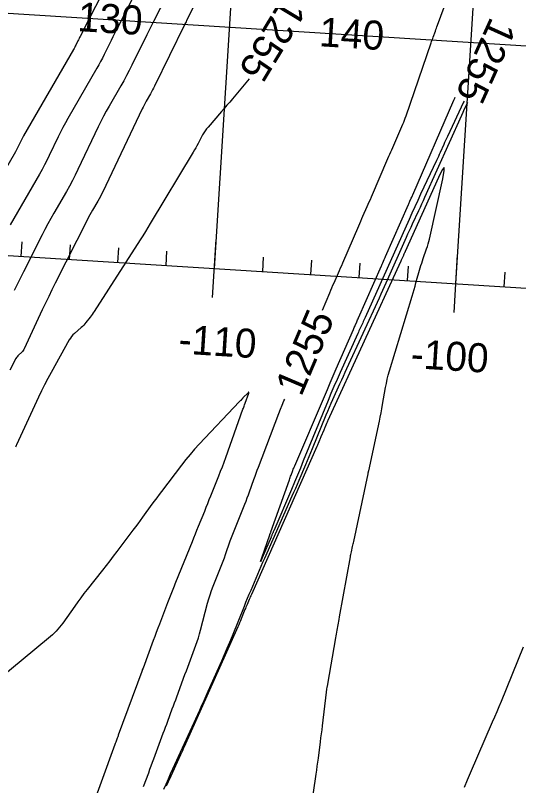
# Model space of a CAD drawing. Extents: x 658976 to 668721, y 639543 to 647196.
# Drawn here: x 661779.9 to 661883.9, y 641733.2 to 641892.5 of the extents above; entities that cross this region are included whole.
import ezdxf

# ---------------------------------------------------------------- set-up
doc = ezdxf.new("R2010")
doc.units = 0
for name, color, linetype in [('Ex_Contour Labels', 7, 'Continuous'), ('Ex_Major Contours', 7, 'Continuous'), ('Ex_Minor Contours', 7, 'Continuous'), ('R_Axis', 7, 'Continuous'), ('R_Axis Annot', 7, 'Continuous'), ('R_Grid', 7, 'Continuous')]:
    doc.layers.add(name, color=color, linetype=linetype)

msp = doc.modelspace()

# ---------------------------------------------------------------- linework, layer by layer
at = {"layer": 'Ex_Major Contours'}
for points in [[(661843.38, 641831.54), (661844.88, 641835.13), (661845.09, 641835.65), (661845.31, 641836.17), (661845.54, 641836.68), (661845.76, 641837.2), (661846.67, 641839.25), (661846.9, 641839.77), (661847.12, 641840.28), (661847.35, 641840.8), (661847.57, 641841.31), (661850.87, 641848.97), (661851.08, 641849.47), (661851.3, 641849.97), (661851.52, 641850.47), (661851.74, 641850.96), (661852.62, 641852.96), (661852.84, 641853.45), (661853.06, 641853.95), (661853.27, 641854.45), (661853.49, 641854.95), (661856.91, 641862.9), (661857.1, 641863.35), (661857.3, 641863.8), (661857.49, 641864.25), (661857.69, 641864.7), (661859.98, 641869.97), (661860.16, 641870.4), (661860.33, 641870.84), (661860.5, 641871.27), (661860.65, 641871.71), (661865.84, 641886.8), (661865.94, 641887.1), (661866.05, 641887.41), (661866.16, 641887.72), (661866.27, 641888.02), (661866.71, 641889.25), (661866.82, 641889.55), (661866.93, 641889.86), (661867.04, 641890.16), (661867.15, 641890.47), (661870.82, 641900.42)], [(661828.23, 641879.36), (661824.76, 641875.24), (661824.2, 641874.57), (661823.64, 641873.91), (661823.07, 641873.25), (661822.51, 641872.59), (661819.75, 641869.4), (661819.43, 641869.01), (661819.14, 641868.61), (661818.86, 641868.19), (661818.61, 641867.76), (661817.66, 641865.98), (661817.41, 641865.54), (661817.17, 641865.1), (661816.92, 641864.67), (661816.66, 641864.23), (661807.79, 641849.43), (661807.28, 641848.6), (661806.77, 641847.77), (661806.25, 641846.94), (661805.73, 641846.11), (661796.19, 641831.26), (661796, 641830.96), (661795.8, 641830.67), (661795.59, 641830.38), (661795.37, 641830.1), (661794.49, 641828.97), (661794.27, 641828.7), (661794.03, 641828.43), (661793.78, 641828.18), (661793.52, 641827.94), (661792.12, 641826.7), (661791.81, 641826.41), (661791.53, 641826.09), (661791.27, 641825.75), (661791.05, 641825.38), (661787.28, 641818.64), (661786.59, 641817.38), (661785.93, 641816.12), (661785.29, 641814.83), (661784.68, 641813.54), (661780.14, 641803.72), (661780.06, 641803.54), (661779.98, 641803.37), (661779.9, 641803.2)], [(661873.33, 641874.45), (661873.28, 641874.33), (661872.99, 641873.7), (661872.69, 641873.07), (661872.4, 641872.43), (661872.12, 641871.8), (661864.49, 641854.81), (661864.18, 641854.12), (661863.87, 641853.43), (661863.55, 641852.74), (661863.23, 641852.05), (661861.94, 641849.3), (661861.62, 641848.61), (661861.3, 641847.92), (661860.98, 641847.23), (661860.67, 641846.54), (661856.46, 641837.14), (661856.11, 641836.37), (661855.76, 641835.59), (661855.41, 641834.82), (661855.06, 641834.05), (661848.37, 641819.43), (661848.01, 641818.63), (661847.64, 641817.83), (661847.28, 641817.03), (661846.92, 641816.22), (661845.47, 641813.02), (661845.11, 641812.22), (661844.76, 641811.41), (661844.41, 641810.6), (661844.08, 641809.79), (661841.22, 641802.84), (661840.89, 641802.02), (661840.55, 641801.2), (661840.2, 641800.38), (661839.86, 641799.56), (661838.47, 641796.3), (661838.12, 641795.48), (661837.77, 641794.67), (661837.41, 641793.86), (661837.06, 641793.05), (661831.37, 641780.17), (661831.01, 641779.35), (661830.65, 641778.52), (661830.29, 641777.7), (661829.94, 641776.87), (661828.54, 641773.55), (661828.19, 641772.72), (661827.84, 641771.89), (661827.5, 641771.06), (661827.16, 641770.22), (661824.7, 641764.12), (661824.17, 641762.82), (661823.63, 641761.54), (661823.08, 641760.25), (661822.52, 641758.98), (661819.7, 641752.66), (661819.26, 641751.69), (661818.83, 641750.72), (661818.39, 641749.75), (661817.95, 641748.78), (661812.41, 641736.64), (661811.93, 641735.58), (661811.45, 641734.52), (661810.98, 641733.47), (661810.5, 641732.41)], [(661806.42, 641733.02), (661807.46, 641735.89), (661807.72, 641736.61), (661807.99, 641737.32), (661808.25, 641738.04), (661808.52, 641738.76), (661810.48, 641744.04), (661810.71, 641744.67), (661810.94, 641745.3), (661811.18, 641745.93), (661811.41, 641746.56), (661812.34, 641749.08), (661812.57, 641749.71), (661812.8, 641750.34), (661813.04, 641750.97), (661813.27, 641751.6), (661814.96, 641756.17), (661815.24, 641756.93), (661815.53, 641757.69), (661815.81, 641758.45), (661816.09, 641759.21), (661817.21, 641762.26), (661817.48, 641763.02), (661817.74, 641763.79), (661817.97, 641764.57), (661818.18, 641765.35), (661819.62, 641770.92), (661819.86, 641771.82), (661820.14, 641772.7), (661820.44, 641773.58), (661820.78, 641774.45), (661822.31, 641778.25), (661822.58, 641778.94), (661822.84, 641779.63), (661823.1, 641780.32), (661823.35, 641781.02), (661824.33, 641783.81), (661824.58, 641784.5), (661824.84, 641785.2), (661825.1, 641785.89), (661825.37, 641786.57), (661827.34, 641791.43), (661827.59, 641792.06), (661827.83, 641792.7), (661828.07, 641793.34), (661828.3, 641793.97), (661829.21, 641796.54), (661829.44, 641797.18), (661829.67, 641797.81), (661829.91, 641798.45), (661830.15, 641799.09), (661834.38, 641810.16), (661834.72, 641811.04), (661835.07, 641811.91), (661835.42, 641812.77), (661835.57, 641813.12)], [(661872.75, 641732.88), (661873.35, 641734.39), (661873.98, 641735.87), (661878.54, 641746.4), (661879, 641747.46), (661879.46, 641748.53), (661879.9, 641749.6), (661880.35, 641750.68), (661884.95, 641761.94)]]:
    msp.add_lwpolyline(points, dxfattribs=at)
at = {"layer": 'Ex_Minor Contours'}
for points in [[(661806.03, 641913.15), (661793.29, 641888.14), (661793.17, 641887.92), (661793.06, 641887.7), (661792.95, 641887.47), (661792.84, 641887.25), (661792.4, 641886.35), (661792.29, 641886.12), (661792.17, 641885.9), (661792.05, 641885.68), (661791.93, 641885.46), (661781.59, 641867.56), (661781.44, 641867.29), (661781.29, 641867.02), (661781.15, 641866.75), (661781.02, 641866.47), (661780.49, 641865.36), (661780.35, 641865.08), (661780.21, 641864.8), (661780.07, 641864.53), (661779.91, 641864.26), (661769.39, 641846.08)], [(661809.07, 641905.8), (661801.13, 641890.23), (661800.77, 641889.51), (661800.4, 641888.78), (661800.04, 641888.05), (661799.69, 641887.33), (661798.26, 641884.41), (661797.9, 641883.68), (661797.53, 641882.97), (661797.14, 641882.25), (661796.74, 641881.55), (661790.76, 641871.2), (661790.24, 641870.26), (661789.72, 641869.31), (661789.23, 641868.35), (661788.76, 641867.39), (661786.9, 641863.49), (661786.43, 641862.52), (661785.94, 641861.57), (661785.43, 641860.62), (661784.9, 641859.68), (661778.81, 641849.17)], [(661812.64, 641899.51), (661808.43, 641891.24), (661808.08, 641890.55), (661807.74, 641889.87), (661807.4, 641889.18), (661807.06, 641888.49), (661803.98, 641882.18), (661803.44, 641881.1), (661802.88, 641880.03), (661802.31, 641878.97), (661801.71, 641877.92), (661799.3, 641873.73), (661798.7, 641872.68), (661798.13, 641871.62), (661797.58, 641870.54), (661797.05, 641869.46), (661792.84, 641860.62), (661792.27, 641859.46), (661791.69, 641858.32), (661791.07, 641857.19), (661790.44, 641856.07), (661787.86, 641851.61), (661787.23, 641850.49), (661786.61, 641849.36), (661786, 641848.23), (661785.41, 641847.08), (661781.57, 641839.49), (661781.09, 641838.52), (661780.61, 641837.54), (661780.14, 641836.56), (661779.68, 641835.58)], [(661816.68, 641894.11), (661815.3, 641891.41), (661815.19, 641891.18), (661815.07, 641890.96), (661814.96, 641890.73), (661814.85, 641890.51), (661808.69, 641877.87), (661808.48, 641877.47), (661808.28, 641877.07), (661808.06, 641876.67), (661807.84, 641876.28), (661806.94, 641874.73), (661806.72, 641874.33), (661806.51, 641873.94), (661806.3, 641873.54), (661806.11, 641873.14), (661797.96, 641856.03), (661797.72, 641855.54), (661797.47, 641855.05), (661797.21, 641854.57), (661796.94, 641854.09), (661795.84, 641852.19), (661795.57, 641851.72), (661795.3, 641851.24), (661795.04, 641850.75), (661794.79, 641850.27), (661788.16, 641837.15), (661787.47, 641835.77), (661786.79, 641834.38), (661786.12, 641832.98), (661785.46, 641831.58), (661781.74, 641823.57), (661781.64, 641823.38), (661781.52, 641823.19), (661781.38, 641823.02), (661781.22, 641822.86), (661780.56, 641822.24), (661780.4, 641822.08), (661780.26, 641821.91), (661780.13, 641821.73), (661780.02, 641821.54), (661778.73, 641819.13)], [(661872.63, 641874.77), (661872.53, 641874.57), (661869.19, 641867.44), (661869, 641867.03), (661868.81, 641866.62), (661868.63, 641866.21), (661868.44, 641865.8), (661867.7, 641864.15), (661867.52, 641863.74), (661867.33, 641863.33), (661867.14, 641862.92), (661866.95, 641862.51), (661863.66, 641855.5), (661863.05, 641854.19), (661862.45, 641852.88), (661861.85, 641851.57), (661861.26, 641850.26), (661852.19, 641830.03), (661852.06, 641829.75), (661851.94, 641829.48), (661851.81, 641829.2), (661851.69, 641828.92), (661851.18, 641827.81), (661851.05, 641827.53), (661850.92, 641827.25), (661850.8, 641826.97), (661850.67, 641826.7), (661847.02, 641818.63), (661846.38, 641817.18), (661845.74, 641815.74), (661845.13, 641814.29), (661844.52, 641812.83), (661839.4, 641800.35), (661838.8, 641798.88), (661838.19, 641797.41), (661837.57, 641795.94), (661836.95, 641794.48), (661833.3, 641785.91), (661833.26, 641785.8), (661833.21, 641785.69), (661833.16, 641785.58), (661833.12, 641785.48), (661832.93, 641785.05), (661832.88, 641784.94), (661832.83, 641784.83), (661832.79, 641784.73), (661832.74, 641784.62), (661830.92, 641780.32), (661830.68, 641779.75), (661830.58, 641779.57), (661830.63, 641779.77), (661830.83, 641780.35), (661832.49, 641785.09), (661832.51, 641785.14), (661832.53, 641785.19), (661832.55, 641785.24), (661832.57, 641785.29), (661832.65, 641785.49), (661832.67, 641785.54), (661832.68, 641785.59), (661832.7, 641785.64), (661832.72, 641785.69), (661836.54, 641796.46), (661836.63, 641796.7), (661836.71, 641796.94), (661836.8, 641797.18), (661836.89, 641797.42), (661837.26, 641798.39), (661837.35, 641798.63), (661837.45, 641798.87), (661837.55, 641799.1), (661837.65, 641799.34), (661843.78, 641813.68), (661844.39, 641815.11), (661845, 641816.54), (661845.62, 641817.96), (661846.24, 641819.39), (661849.78, 641827.53), (661849.87, 641827.73), (661849.96, 641827.93), (661850.04, 641828.13), (661850.13, 641828.34), (661850.46, 641829.14), (661850.55, 641829.35), (661850.63, 641829.55), (661850.72, 641829.75), (661850.81, 641829.95), (661855.57, 641840.71), (661855.64, 641840.87), (661855.71, 641841.03), (661855.78, 641841.18), (661855.85, 641841.34), (661856.12, 641841.98), (661856.19, 641842.14), (661856.26, 641842.3), (661856.33, 641842.45), (661856.4, 641842.61), (661861.16, 641853.38), (661861.23, 641853.54), (661861.3, 641853.71), (661861.38, 641853.88), (661861.45, 641854.05), (661861.74, 641854.73), (661861.81, 641854.9), (661861.89, 641855.06), (661861.96, 641855.23), (661862.03, 641855.4), (661870.53, 641874.97), (661870.7, 641875.37), (661870.79, 641875.6)], [(661840.37, 641723.72), (661842.07, 641735.57), (661842.19, 641736.41), (661842.31, 641737.24), (661842.42, 641738.08), (661842.53, 641738.92), (661842.97, 641742.26), (661843.07, 641743.1), (661843.18, 641743.94), (661843.28, 641744.77), (661843.38, 641745.61), (661844.2, 641752.52), (661844.22, 641752.66), (661844.24, 641752.8), (661844.26, 641752.94), (661844.28, 641753.08), (661844.38, 641753.63), (661844.4, 641753.76), (661844.42, 641753.9), (661844.45, 641754.04), (661844.47, 641754.18), (661846.12, 641763.78), (661846.19, 641764.17), (661846.26, 641764.56), (661846.33, 641764.95), (661846.4, 641765.34), (661846.81, 641767.6), (661846.83, 641767.73), (661846.87, 641767.95), (661846.88, 641768.03), (661846.9, 641768.12), (661849.14, 641780.51), (661849.19, 641780.78), (661849.24, 641781.04), (661849.3, 641781.31), (661849.36, 641781.58), (661849.6, 641782.65), (661849.66, 641782.92), (661849.72, 641783.18), (661849.78, 641783.45), (661849.84, 641783.72), (661852.8, 641797.66), (661852.81, 641797.72), (661852.82, 641797.77), (661852.83, 641797.83), (661852.84, 641797.88), (661852.89, 641798.1), (661852.9, 641798.15), (661852.91, 641798.21), (661852.92, 641798.26), (661852.93, 641798.32), (661855.13, 641808.55), (661855.31, 641809.42), (661855.48, 641810.29), (661855.65, 641811.16), (661855.8, 641812.03), (661856.41, 641815.52), (661856.58, 641816.39), (661856.77, 641817.26), (661856.98, 641818.11), (661857.23, 641818.97), (661861.9, 641834.44), (661862.1, 641835.12), (661862.3, 641835.8), (661862.5, 641836.48), (661862.7, 641837.17), (661863.59, 641840.26), (661863.73, 641840.76), (661863.89, 641841.26), (661864.05, 641841.76), (661864.22, 641842.25), (661864.9, 641844.23), (661865.07, 641844.72), (661865.22, 641845.22), (661865.35, 641845.72), (661865.47, 641846.23), (661868.24, 641858.71), (661868.56, 641860.41), (661868.52, 641861.03), (661868.12, 641860.56), (661867.36, 641859), (661860.47, 641843.66), (661860.44, 641843.59), (661860.41, 641843.52), (661860.38, 641843.45), (661860.35, 641843.38), (661860.22, 641843.1), (661860.18, 641843.03), (661860.15, 641842.96), (661860.12, 641842.89), (661860.09, 641842.82), (661859.66, 641841.87), (661859.62, 641841.79), (661859.59, 641841.71), (661859.55, 641841.63), (661859.52, 641841.55), (661844.51, 641808.73), (661844.44, 641808.57), (661844.36, 641808.4), (661844.29, 641808.24), (661844.21, 641808.07), (661843.92, 641807.41), (661843.84, 641807.25), (661843.77, 641807.08), (661843.7, 641806.92), (661843.63, 641806.75), (661843.04, 641805.32), (661842.98, 641805.15), (661842.91, 641804.99), (661842.83, 641804.82), (661842.76, 641804.65), (661842.48, 641803.98), (661842.41, 641803.81), (661842.33, 641803.65), (661842.26, 641803.48), (661842.19, 641803.31), (661828.68, 641772.73), (661828.56, 641772.48), (661828.45, 641772.22), (661828.34, 641771.96), (661828.23, 641771.7), (661827.79, 641770.66), (661827.68, 641770.4), (661827.57, 641770.14), (661827.46, 641769.87), (661827.36, 641769.61), (661826.59, 641767.7), (661826.42, 641767.29), (661826.25, 641766.89), (661826.08, 641766.49), (661825.9, 641766.08), (661814.79, 641741.21), (661814.61, 641740.8), (661814.42, 641740.39), (661814.24, 641739.98), (661814.05, 641739.57), (661811.71, 641734.42), (661811.5, 641733.97), (661811.3, 641733.52), (661811.1, 641733.08)], [(661794.62, 641725.43), (661800.54, 641741.8), (661800.6, 641741.96), (661800.66, 641742.12), (661800.72, 641742.28), (661800.78, 641742.44), (661801.01, 641743.07), (661801.07, 641743.23), (661801.13, 641743.39), (661801.19, 641743.55), (661801.25, 641743.71), (661806.12, 641756.91), (661806.14, 641756.97), (661806.16, 641757.03), (661806.18, 641757.08), (661806.2, 641757.14), (661806.29, 641757.36), (661806.31, 641757.42), (661806.33, 641757.47), (661806.35, 641757.53), (661806.37, 641757.59), (661808.46, 641763.26), (661808.78, 641764.11), (661809.1, 641764.96), (661809.42, 641765.81), (661809.74, 641766.66), (661811.41, 641771.06), (661811.55, 641771.41), (661811.68, 641771.76), (661811.82, 641772.11), (661811.96, 641772.46), (661812.52, 641773.86), (661812.66, 641774.21), (661812.81, 641774.56), (661812.95, 641774.91), (661813.09, 641775.26), (661816.49, 641783.69), (661816.81, 641784.48), (661817.13, 641785.26), (661817.44, 641786.05), (661817.76, 641786.84), (661819.03, 641789.99), (661819.34, 641790.78), (661819.66, 641791.57), (661819.98, 641792.36), (661820.3, 641793.15), (661821.96, 641797.26), (661822.33, 641798.21), (661822.7, 641799.16), (661823.06, 641800.12), (661823.41, 641801.08), (661826.95, 641811.05), (661827.03, 641811.27), (661827.11, 641811.49), (661827.19, 641811.71), (661827.27, 641811.93), (661827.62, 641812.87), (661827.69, 641813.06), (661827.76, 641813.25), (661827.82, 641813.44), (661827.89, 641813.63), (661828.14, 641814.38), (661828.18, 641814.53), (661828.17, 641814.59), (661828.11, 641814.57), (661828, 641814.47), (661826.95, 641813.38), (661826.89, 641813.32), (661826.83, 641813.25), (661826.78, 641813.19), (661826.72, 641813.13), (661826.48, 641812.88), (661826.42, 641812.82), (661826.37, 641812.75), (661826.31, 641812.69), (661826.25, 641812.63), (661817.9, 641803.83), (661816.94, 641802.79), (661816.01, 641801.72), (661815.11, 641800.63), (661814.24, 641799.51), (661810.11, 641794.06), (661809.61, 641793.39), (661809.11, 641792.73), (661808.62, 641792.06), (661808.13, 641791.39), (661806.18, 641788.7), (661805.69, 641788.03), (661805.2, 641787.37), (661804.7, 641786.7), (661804.2, 641786.03), (661800.87, 641781.6), (661800.14, 641780.65), (661799.41, 641779.69), (661798.67, 641778.75), (661797.93, 641777.8), (661794.73, 641773.78), (661794.07, 641772.93), (661793.42, 641772.08), (661792.78, 641771.21), (661792.16, 641770.34), (661789.68, 641766.82), (661789.04, 641765.97), (661788.34, 641765.16), (661787.59, 641764.41), (661786.78, 641763.7), (661776.18, 641755.03)]]:
    msp.add_lwpolyline(points, dxfattribs=at)
at = {"layer": 'R_Axis'}
for p, q in [((661621.43, 641852.69), (663118.48, 641758.67)), ((661781.12, 641842.66), (661781.3, 641845.65)), ((661820.66, 641834.16), (661821.41, 641846.14)), ((661791.1, 641842.03), (661791.28, 641845.03)), ((661801.08, 641841.41), (661801.26, 641844.4)), ((661811.06, 641840.78), (661811.24, 641843.77)), ((661831.02, 641839.53), (661831.2, 641842.52)), ((661870.56, 641831.03), (661871.31, 641843.01)), ((661841, 641838.9), (661841.19, 641841.89)), ((661850.98, 641838.27), (661851.17, 641841.27)), ((661860.96, 641837.65), (661861.15, 641840.64)), ((661880.92, 641836.39), (661881.11, 641839.39))]:
    msp.add_line(p, q, dxfattribs=at)
at = {"layer": 'R_Grid'}
for p, q in [((661821.04, 641840.15), (661836.71, 642089.66)), ((661870.94, 641837.02), (661886.61, 642086.53)), ((661624.56, 641902.59), (663121.61, 641808.57)), ((661621.43, 641852.69), (663118.48, 641758.67))]:
    msp.add_line(p, q, dxfattribs=at)

# ---------------------------------------------------------------- texts
at = {"layer": 'Ex_Contour Labels'}
for rotation, p in [(238.8305, (661835.15, 641896.6)), (245.6525, (661878.16, 641892.39)), (67.0174, (661838.98, 641813.49))]:
    msp.add_text('1255', height=6, rotation=rotation, dxfattribs=at).set_placement(p)
at = {"layer": 'R_Axis Annot'}
for s, p in [('130', (661792.65, 641889.26)), ('140', (661842.56, 641886.13)), ('-110', (661813.52, 641822.59)), ('-100', (661861.49, 641819.58))]:
    msp.add_text(s, height=6, rotation=356.4063, dxfattribs=at).set_placement(p)

doc.saveas('drawing.dxf')
